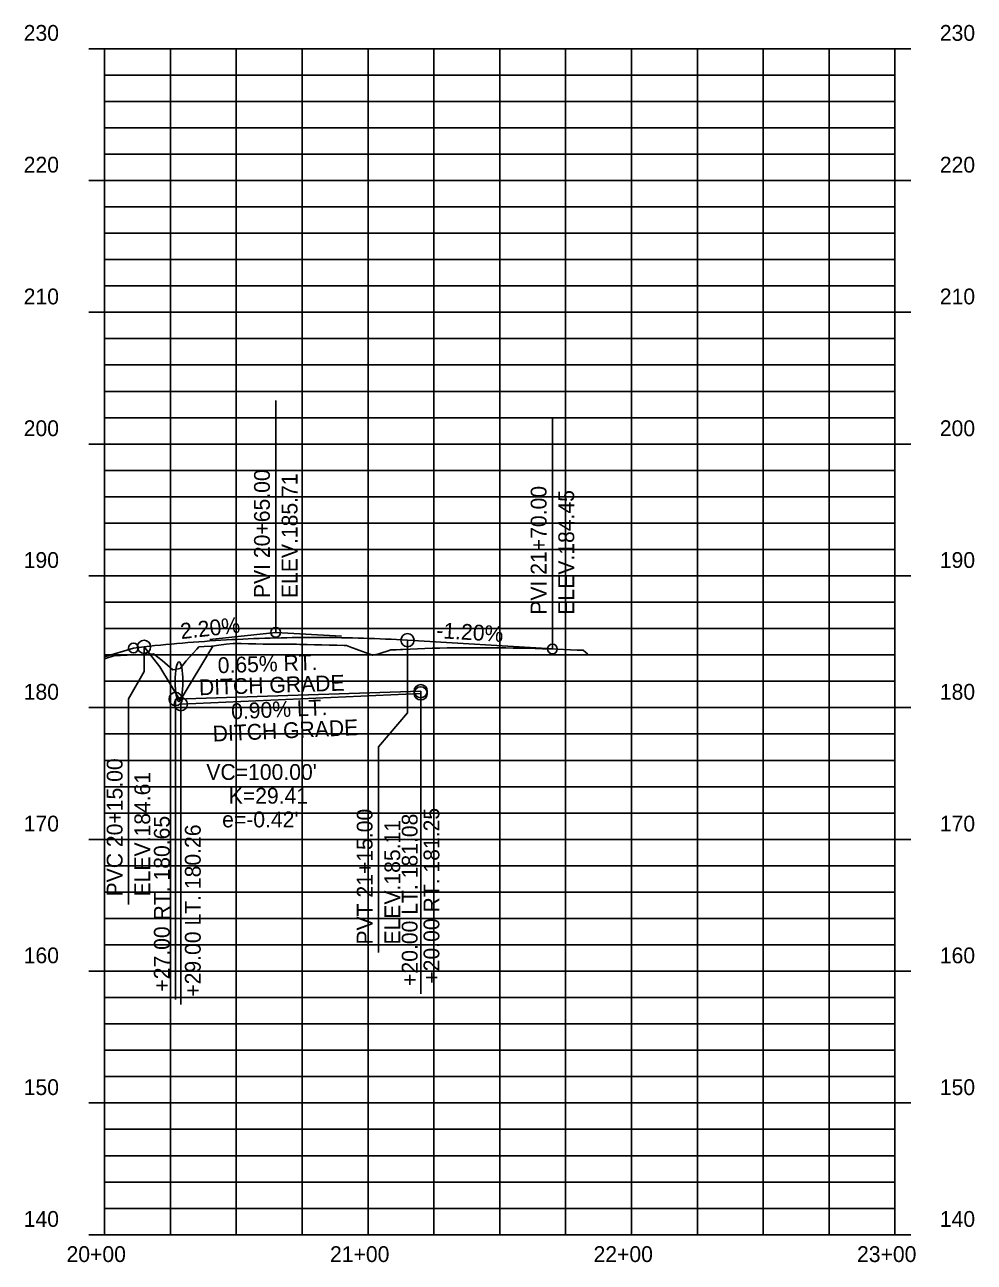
# Model space of a CAD drawing. Extents: x 1409239 to 1412142, y 1838831 to 1842626.
# Drawn here: x 1410886.1 to 1411246.5, y 1839787.1 to 1840256.7 of the extents above; entities that cross this region are included whole.
import ezdxf

# ---------------------------------------------------------------- set-up
doc = ezdxf.new("R2010")
doc.units = 0
for name, color, linetype in [('63', 7, 'Continuous'), ('R_Axis_Annotation', 7, 'Continuous'), ('R_Drainage', 7, 'Continuous'), ('R_Exist Surface', 7, 'Continuous'), ('R_Grid', 7, 'Continuous'), ('R_Grid Annot', 7, 'Continuous'), ('R_Grid_Minor', 7, 'Continuous'), ('R_Prop Surface', 7, 'Continuous'), ('R_Vert Alg', 7, 'Continuous'), ('R_Vert Alg Annot', 7, 'Continuous')]:
    doc.layers.add(name, color=color, linetype=linetype)

msp = doc.modelspace()

# ---------------------------------------------------------------- linework, layer by layer
at = {"layer": 'R_Drainage'}
msp.add_ellipse((1410944.67, 1840007.43), major_axis=(0, 7.5), ratio=0.2, dxfattribs=at)
at = {"layer": 'R_Exist Surface'}
msp.add_lwpolyline([(1410916.4, 1840016.13), (1410916.76, 1840016.26), (1410919.88, 1840017.22), (1410927.59, 1840017.57), (1410929.73, 1840017.66), (1410931.27, 1840017.77), (1410934.99, 1840018.01), (1410938.33, 1840015.45), (1410942.39, 1840011.96), (1410944.45, 1840012.28), (1410945.06, 1840012.37), (1410947.43, 1840015.3), (1410948.67, 1840016.67), (1410951.46, 1840019.75), (1410952.22, 1840020.59), (1410954.25, 1840020.73), (1410957.05, 1840020.91), (1410957.21, 1840020.92), (1410959.84, 1840021.26), (1410962.63, 1840021.63), (1410965.23, 1840021.96), (1410965.42, 1840021.96), (1410968.21, 1840021.89), (1410971.01, 1840021.82), (1410973.8, 1840021.74), (1410976.59, 1840021.67), (1410976.87, 1840021.67), (1410977.22, 1840021.67), (1410977.78, 1840021.66), (1410979.38, 1840021.65), (1410982.17, 1840021.64), (1410984.97, 1840021.63), (1410987.76, 1840021.61), (1410989.27, 1840021.6), (1410990.55, 1840021.57), (1410993.34, 1840021.51), (1410996.13, 1840021.45), (1410996.56, 1840021.44), (1410998.93, 1840021.38), (1411001.72, 1840021.32), (1411004.51, 1840021.25), (1411007.3, 1840021.18), (1411008.22, 1840021.16), (1411010.09, 1840020.44), (1411010.85, 1840020.15), (1411012.88, 1840019.38), (1411015.68, 1840018.34), (1411018.1, 1840017.47), (1411018.47, 1840017.55), (1411020.1, 1840017.89), (1411021.26, 1840018.28), (1411024.05, 1840019.17), (1411025.12, 1840019.5), (1411026.84, 1840019.53), (1411027.09, 1840019.53), (1411028.79, 1840019.6), (1411029.64, 1840019.65), (1411032.43, 1840019.78), (1411035.22, 1840019.9), (1411038.01, 1840020.01), (1411040.8, 1840020.11), (1411042.98, 1840020.17), (1411043.6, 1840020.18), (1411046.39, 1840020.22), (1411049.18, 1840020.25), (1411051.97, 1840020.27), (1411053.1, 1840020.27), (1411054.76, 1840020.29), (1411057.56, 1840020.31), (1411059.87, 1840020.31), (1411060.35, 1840020.31), (1411063.14, 1840020.3), (1411065.93, 1840020.27), (1411068.72, 1840020.24), (1411071.52, 1840020.19), (1411074.31, 1840020.13), (1411075.49, 1840020.11), (1411077.1, 1840020.09), (1411077.59, 1840020.08), (1411079.89, 1840020.02), (1411082.68, 1840019.93), (1411085.48, 1840019.83), (1411095.83, 1840019.43), (1411098.03, 1840019.38), (1411099.87, 1840017.91)], dxfattribs=at)
at = {"layer": 'R_Grid'}
for p, q in [((1410916.4, 1839797.57), (1410916.4, 1840247.57)), ((1410916.4, 1840247.57), (1411216.4, 1840247.57)), ((1410916.4, 1840247.57), (1411216.4, 1840247.57)), ((1411016.4, 1839797.57), (1411016.4, 1840247.57)), ((1411116.4, 1839797.57), (1411116.4, 1840247.57)), ((1411216.4, 1839797.57), (1411216.4, 1840247.57)), ((1410916.4, 1840197.57), (1411216.4, 1840197.57)), ((1410916.4, 1840147.57), (1411216.4, 1840147.57)), ((1410916.4, 1840097.57), (1411216.4, 1840097.57)), ((1410916.4, 1840047.57), (1411216.4, 1840047.57)), ((1410916.4, 1839997.57), (1411216.4, 1839997.57)), ((1410916.4, 1839947.57), (1411216.4, 1839947.57)), ((1410916.4, 1839897.57), (1411216.4, 1839897.57)), ((1410916.4, 1839847.57), (1411216.4, 1839847.57)), ((1410916.4, 1839797.57), (1411216.4, 1839797.57))]:
    msp.add_line(p, q, dxfattribs=at)
at = {"layer": 'R_Grid Annot'}
for p, q in [((1410910.4, 1840247.57), (1410916.4, 1840247.57)), ((1410910.4, 1840247.57), (1410916.4, 1840247.57)), ((1411222.4, 1840247.57), (1411216.4, 1840247.57)), ((1411222.4, 1840247.57), (1411216.4, 1840247.57)), ((1410916.4, 1840237.57), (1410919.4, 1840237.57)), ((1411216.4, 1840237.57), (1411213.4, 1840237.57)), ((1410916.4, 1840227.57), (1410919.4, 1840227.57)), ((1411216.4, 1840227.57), (1411213.4, 1840227.57)), ((1410916.4, 1840217.57), (1410919.4, 1840217.57)), ((1411216.4, 1840217.57), (1411213.4, 1840217.57)), ((1410916.4, 1840207.57), (1410919.4, 1840207.57)), ((1411216.4, 1840207.57), (1411213.4, 1840207.57)), ((1410910.4, 1840197.57), (1410916.4, 1840197.57)), ((1411222.4, 1840197.57), (1411216.4, 1840197.57)), ((1410916.4, 1840187.57), (1410919.4, 1840187.57)), ((1411216.4, 1840187.57), (1411213.4, 1840187.57)), ((1410916.4, 1840177.57), (1410919.4, 1840177.57)), ((1411216.4, 1840177.57), (1411213.4, 1840177.57)), ((1410916.4, 1840167.57), (1410919.4, 1840167.57)), ((1411216.4, 1840167.57), (1411213.4, 1840167.57)), ((1410916.4, 1840157.57), (1410919.4, 1840157.57)), ((1411216.4, 1840157.57), (1411213.4, 1840157.57)), ((1410910.4, 1840147.57), (1410916.4, 1840147.57)), ((1411222.4, 1840147.57), (1411216.4, 1840147.57)), ((1410916.4, 1840137.57), (1410919.4, 1840137.57)), ((1411216.4, 1840137.57), (1411213.4, 1840137.57)), ((1410916.4, 1840127.57), (1410919.4, 1840127.57)), ((1411216.4, 1840127.57), (1411213.4, 1840127.57)), ((1410916.4, 1840117.57), (1410919.4, 1840117.57)), ((1411216.4, 1840117.57), (1411213.4, 1840117.57)), ((1410916.4, 1840107.57), (1410919.4, 1840107.57)), ((1411216.4, 1840107.57), (1411213.4, 1840107.57)), ((1410910.4, 1840097.57), (1410916.4, 1840097.57)), ((1411222.4, 1840097.57), (1411216.4, 1840097.57)), ((1410916.4, 1840087.57), (1410919.4, 1840087.57)), ((1411216.4, 1840087.57), (1411213.4, 1840087.57)), ((1410916.4, 1840077.57), (1410919.4, 1840077.57)), ((1411216.4, 1840077.57), (1411213.4, 1840077.57)), ((1410916.4, 1840067.57), (1410919.4, 1840067.57)), ((1411216.4, 1840067.57), (1411213.4, 1840067.57)), ((1410916.4, 1840057.57), (1410919.4, 1840057.57)), ((1411216.4, 1840057.57), (1411213.4, 1840057.57)), ((1410910.4, 1840047.57), (1410916.4, 1840047.57)), ((1411222.4, 1840047.57), (1411216.4, 1840047.57)), ((1410916.4, 1840037.57), (1410919.4, 1840037.57)), ((1411216.4, 1840037.57), (1411213.4, 1840037.57)), ((1410916.4, 1840027.57), (1410919.4, 1840027.57)), ((1411216.4, 1840027.57), (1411213.4, 1840027.57)), ((1410916.4, 1840017.57), (1410919.4, 1840017.57)), ((1411216.4, 1840017.57), (1411213.4, 1840017.57)), ((1410916.4, 1840007.57), (1410919.4, 1840007.57)), ((1411216.4, 1840007.57), (1411213.4, 1840007.57)), ((1410910.4, 1839997.57), (1410916.4, 1839997.57)), ((1411222.4, 1839997.57), (1411216.4, 1839997.57)), ((1410916.4, 1839987.57), (1410919.4, 1839987.57)), ((1411216.4, 1839987.57), (1411213.4, 1839987.57)), ((1410916.4, 1839977.57), (1410919.4, 1839977.57)), ((1411216.4, 1839977.57), (1411213.4, 1839977.57)), ((1410916.4, 1839967.57), (1410919.4, 1839967.57)), ((1411216.4, 1839967.57), (1411213.4, 1839967.57)), ((1410916.4, 1839957.57), (1410919.4, 1839957.57)), ((1411216.4, 1839957.57), (1411213.4, 1839957.57)), ((1410910.4, 1839947.57), (1410916.4, 1839947.57)), ((1411222.4, 1839947.57), (1411216.4, 1839947.57)), ((1410916.4, 1839937.57), (1410919.4, 1839937.57)), ((1411216.4, 1839937.57), (1411213.4, 1839937.57)), ((1410916.4, 1839927.57), (1410919.4, 1839927.57)), ((1411216.4, 1839927.57), (1411213.4, 1839927.57)), ((1410916.4, 1839917.57), (1410919.4, 1839917.57)), ((1411216.4, 1839917.57), (1411213.4, 1839917.57)), ((1410916.4, 1839907.57), (1410919.4, 1839907.57)), ((1411216.4, 1839907.57), (1411213.4, 1839907.57)), ((1410910.4, 1839897.57), (1410916.4, 1839897.57)), ((1411222.4, 1839897.57), (1411216.4, 1839897.57)), ((1410916.4, 1839887.57), (1410919.4, 1839887.57)), ((1411216.4, 1839887.57), (1411213.4, 1839887.57)), ((1410916.4, 1839877.57), (1410919.4, 1839877.57)), ((1411216.4, 1839877.57), (1411213.4, 1839877.57)), ((1410916.4, 1839867.57), (1410919.4, 1839867.57)), ((1411216.4, 1839867.57), (1411213.4, 1839867.57)), ((1410916.4, 1839857.57), (1410919.4, 1839857.57)), ((1411216.4, 1839857.57), (1411213.4, 1839857.57)), ((1410910.4, 1839847.57), (1410916.4, 1839847.57)), ((1411222.4, 1839847.57), (1411216.4, 1839847.57)), ((1410916.4, 1839837.57), (1410919.4, 1839837.57)), ((1411216.4, 1839837.57), (1411213.4, 1839837.57)), ((1410916.4, 1839827.57), (1410919.4, 1839827.57)), ((1411216.4, 1839827.57), (1411213.4, 1839827.57)), ((1410916.4, 1839817.57), (1410919.4, 1839817.57)), ((1411216.4, 1839817.57), (1411213.4, 1839817.57)), ((1410916.4, 1839807.57), (1410919.4, 1839807.57)), ((1411216.4, 1839807.57), (1411213.4, 1839807.57)), ((1410910.4, 1839797.57), (1410916.4, 1839797.57)), ((1411222.4, 1839797.57), (1411216.4, 1839797.57))]:
    msp.add_line(p, q, dxfattribs=at)
at = {"layer": 'R_Grid_Minor'}
for p, q in [((1410941.4, 1839797.57), (1410941.4, 1840247.57)), ((1410966.4, 1839797.57), (1410966.4, 1840247.57)), ((1410991.4, 1839797.57), (1410991.4, 1840247.57)), ((1411041.4, 1839797.57), (1411041.4, 1840247.57)), ((1411066.4, 1839797.57), (1411066.4, 1840247.57)), ((1411091.4, 1839797.57), (1411091.4, 1840247.57)), ((1411141.4, 1839797.57), (1411141.4, 1840247.57)), ((1411166.4, 1839797.57), (1411166.4, 1840247.57)), ((1411191.4, 1839797.57), (1411191.4, 1840247.57)), ((1410916.4, 1840237.57), (1411216.4, 1840237.57)), ((1410916.4, 1840227.57), (1411216.4, 1840227.57)), ((1410916.4, 1840217.57), (1411216.4, 1840217.57)), ((1410916.4, 1840207.57), (1411216.4, 1840207.57)), ((1410916.4, 1840187.57), (1411216.4, 1840187.57)), ((1410916.4, 1840177.57), (1411216.4, 1840177.57)), ((1410916.4, 1840167.57), (1411216.4, 1840167.57)), ((1410916.4, 1840157.57), (1411216.4, 1840157.57)), ((1410916.4, 1840137.57), (1411216.4, 1840137.57)), ((1410916.4, 1840127.57), (1411216.4, 1840127.57)), ((1410916.4, 1840117.57), (1411216.4, 1840117.57)), ((1410916.4, 1840107.57), (1411216.4, 1840107.57)), ((1410916.4, 1840087.57), (1411216.4, 1840087.57)), ((1410916.4, 1840077.57), (1411216.4, 1840077.57)), ((1410916.4, 1840067.57), (1411216.4, 1840067.57)), ((1410916.4, 1840057.57), (1411216.4, 1840057.57)), ((1410916.4, 1840037.57), (1411216.4, 1840037.57)), ((1410916.4, 1840027.57), (1411216.4, 1840027.57)), ((1410916.4, 1840017.57), (1411216.4, 1840017.57)), ((1410916.4, 1840007.57), (1411216.4, 1840007.57)), ((1410916.4, 1839987.57), (1411216.4, 1839987.57)), ((1410916.4, 1839977.57), (1411216.4, 1839977.57)), ((1410916.4, 1839967.57), (1411216.4, 1839967.57)), ((1410916.4, 1839957.57), (1411216.4, 1839957.57)), ((1410916.4, 1839937.57), (1411216.4, 1839937.57)), ((1410916.4, 1839927.57), (1411216.4, 1839927.57)), ((1410916.4, 1839917.57), (1411216.4, 1839917.57)), ((1410916.4, 1839907.57), (1411216.4, 1839907.57)), ((1410916.4, 1839887.57), (1411216.4, 1839887.57)), ((1410916.4, 1839877.57), (1411216.4, 1839877.57)), ((1410916.4, 1839867.57), (1411216.4, 1839867.57)), ((1410916.4, 1839857.57), (1411216.4, 1839857.57)), ((1410916.4, 1839837.57), (1411216.4, 1839837.57)), ((1410916.4, 1839827.57), (1411216.4, 1839827.57)), ((1410916.4, 1839817.57), (1411216.4, 1839817.57)), ((1410916.4, 1839807.57), (1411216.4, 1839807.57))]:
    msp.add_line(p, q, dxfattribs=at)
at = {"layer": 'R_Prop Surface'}
for p, q in [((1410931.4, 1840020.63), (1410937.42, 1840013.1)), ((1410945.12, 1840000.27), (1410957.52, 1840020.94)), ((1410937.42, 1840013.1), (1410945.12, 1840000.27))]:
    msp.add_line(p, q, dxfattribs=at)
msp.add_lwpolyline([(1410916.4, 1840016.8), (1410927.4, 1840020.19), (1410931.4, 1840020.63)], dxfattribs=at)
at = {"layer": 'R_Vert Alg'}
for p, q in [((1410927.4, 1840020.19), (1410931.4, 1840020.63)), ((1411031.4, 1840023.13), (1411086.4, 1840019.83)), ((1410943.4, 1840000.82), (1411036.4, 1840003.84)), ((1410945.4, 1839998.89), (1411036.4, 1840002.98))]:
    msp.add_line(p, q, dxfattribs=at)
msp.add_lwpolyline([(1410931.4, 1840020.63), (1410933.48, 1840020.86), (1410935.56, 1840021.08), (1410937.65, 1840021.29), (1410939.73, 1840021.49), (1410941.81, 1840021.69), (1410943.9, 1840021.88), (1410945.98, 1840022.06), (1410948.06, 1840022.23), (1410950.15, 1840022.4), (1410952.23, 1840022.56), (1410954.31, 1840022.71), (1410956.4, 1840022.85), (1410958.48, 1840022.99), (1410960.56, 1840023.12), (1410962.65, 1840023.24), (1410964.73, 1840023.36), (1410966.81, 1840023.46), (1410968.9, 1840023.56), (1410970.98, 1840023.66), (1410973.06, 1840023.74), (1410975.15, 1840023.82), (1410977.23, 1840023.89), (1410979.31, 1840023.95), (1410983.48, 1840024.06), (1410985.56, 1840024.1), (1410987.65, 1840024.13), (1410989.73, 1840024.16), (1410991.81, 1840024.18), (1410993.9, 1840024.19), (1410995.98, 1840024.19), (1410998.06, 1840024.19), (1411000.15, 1840024.18), (1411002.23, 1840024.16), (1411004.31, 1840024.14), (1411006.4, 1840024.1), (1411008.48, 1840024.06), (1411010.56, 1840024.01), (1411012.65, 1840023.96), (1411014.73, 1840023.9), (1411016.81, 1840023.83), (1411018.9, 1840023.75), (1411020.98, 1840023.67), (1411023.06, 1840023.57), (1411025.15, 1840023.48), (1411027.23, 1840023.37), (1411029.31, 1840023.25), (1411031.4, 1840023.13)], dxfattribs=at)
at = {"layer": 'R_Vert Alg Annot'}
for p, q in [((1410981.4, 1840036.13), (1410981.4, 1840114.13)), ((1411086.4, 1840029.83), (1411086.4, 1840107.83)), ((1410981.4, 1840026.13), (1410981.4, 1840036.13)), ((1411086.4, 1840019.83), (1411086.4, 1840029.83)), ((1410956.4, 1840023.38), (1410981.4, 1840026.13)), ((1410981.4, 1840026.13), (1411006.4, 1840024.63)), ((1410931.4, 1840020.63), (1410931.4, 1840011.32)), ((1411031.4, 1840023.13), (1411031.4, 1839995.55)), ((1410925.5, 1840000.92), (1410931.4, 1840011.32)), ((1411036.4, 1840003.84), (1411036.4, 1839973.84)), ((1411036.4, 1840002.98), (1411036.4, 1839972.98)), ((1410925.5, 1840000.92), (1410925.5, 1839922.92)), ((1410943.4, 1840000.82), (1410943.4, 1839970.82)), ((1410945.4, 1839998.89), (1410945.4, 1839968.89)), ((1411020.38, 1839982.67), (1411031.4, 1839995.55)), ((1411020.38, 1839982.67), (1411020.38, 1839904.67)), ((1411036.4, 1839973.84), (1411036.4, 1839889.84)), ((1411036.4, 1839972.98), (1411036.4, 1839888.98)), ((1410943.4, 1839970.82), (1410943.4, 1839886.82)), ((1410945.4, 1839968.89), (1410945.4, 1839884.89))]:
    msp.add_line(p, q, dxfattribs=at)
for centre, radius in [((1410981.4, 1840026.13), 1.85), ((1411031.4, 1840023.13), 2.5), ((1410927.4, 1840020.19), 1.85), ((1410931.4, 1840020.63), 2.5), ((1411086.4, 1840019.83), 1.85), ((1411036.4, 1840003.84), 2.5), ((1410943.4, 1840000.82), 2.5), ((1410945.4, 1839998.89), 2.5), ((1411036.4, 1840002.98), 2.5)]:
    msp.add_circle(centre, radius, dxfattribs=at)

# ---------------------------------------------------------------- texts
at = {"layer": '63'}
msp.add_text('-', height=0.0001, dxfattribs=at).set_placement((1410916.4, 1839797.57))
at = {"layer": 'R_Axis_Annotation'}
for s, p in [('230', (1410885.73, 1840250.57)), ('230', (1410885.73, 1840250.57)), ('230', (1411233.41, 1840250.57)), ('230', (1411233.41, 1840250.57)), ('220', (1410885.73, 1840200.57)), ('220', (1411233.41, 1840200.57)), ('210', (1410885.73, 1840150.57)), ('210', (1411233.41, 1840150.57)), ('200', (1410885.73, 1840100.57)), ('200', (1411233.41, 1840100.57)), ('190', (1410885.73, 1840050.57)), ('190', (1411233.41, 1840050.57)), ('180', (1410885.73, 1840000.57)), ('180', (1411233.41, 1840000.57)), ('170', (1410885.73, 1839950.57)), ('170', (1411233.41, 1839950.57)), ('160', (1410885.73, 1839900.57)), ('160', (1411233.41, 1839900.57)), ('150', (1410885.73, 1839850.57)), ('150', (1411233.41, 1839850.57)), ('140', (1410885.73, 1839800.57)), ('140', (1411233.41, 1839800.57)), ('20+00', (1410901.99, 1839787.22)), ('21+00', (1411001.99, 1839787.22)), ('22+00', (1411101.99, 1839787.22)), ('23+00', (1411201.99, 1839787.22))]:
    msp.add_text(s, height=6, dxfattribs=at).set_placement(p)
at = {"layer": 'R_Vert Alg Annot'}
for s, rotation, p in [('PVI 20+65.00', 90, (1410979.15, 1840039.13)), ('ELEV.185.71', 90, (1410989.65, 1840039.13)), ('PVI 21+70.00', 90, (1411084.15, 1840032.83)), ('ELEV.184.45', 90, (1411094.65, 1840032.83)), ('2.20%', 6.2773, (1410945.51, 1840023.56)), ('-1.20%', 356.5664, (1411042.22, 1840023.99)), ('0.65% RT. ', 1.8615, (1410959.45, 1840010.61)), ('DITCH GRADE', 1.8615, (1410952.34, 1840002.25)), ('0.90% LT. ', 2.5766, (1410964.59, 1839993.12)), ('DITCH GRADE', 2.5766, (1410957.59, 1839984.67)), ('PVC 20+15.00', 90, (1410923.25, 1839925.92)), ('ELEV.184.61', 90, (1410933.75, 1839925.92)), ('+20.00 RT. 181.25', 90, (1411043.48, 1839892.84)), ('+27.00 RT. 180.65', 90, (1410941.15, 1839889.82)), ('PVT 21+15.00', 90, (1411018.13, 1839907.67)), ('ELEV.185.11', 90, (1411028.63, 1839907.67)), ('+20.00 LT. 181.08', 90, (1411035.21, 1839891.98)), ('+29.00 LT. 180.26', 90, (1410952.91, 1839887.89))]:
    msp.add_text(s, height=6, rotation=rotation, dxfattribs=at).set_placement(p)
for s, p in [("VC=100.00'", (1410955.05, 1839970.14)), ('K=29.41', (1410963.54, 1839961.14)), ("e=-0.42'", (1410961.05, 1839952.14))]:
    msp.add_text(s, height=6, dxfattribs=at).set_placement(p)

doc.saveas('drawing.dxf')
